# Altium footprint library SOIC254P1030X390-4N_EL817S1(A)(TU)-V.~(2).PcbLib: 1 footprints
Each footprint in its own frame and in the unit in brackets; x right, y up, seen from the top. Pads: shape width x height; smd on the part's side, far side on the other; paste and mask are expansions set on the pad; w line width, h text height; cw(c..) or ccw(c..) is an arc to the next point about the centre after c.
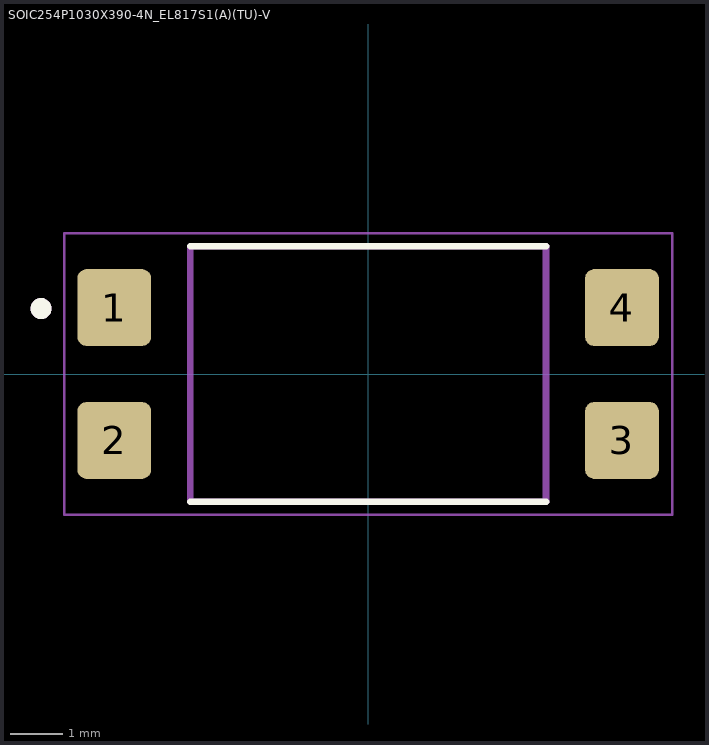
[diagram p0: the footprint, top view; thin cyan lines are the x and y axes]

## SOIC254P1030X390-4N_EL817S1(A)(TU)-V [mm]
pads (4):
  rrect25% 1.41x1.47 smd: 1(-4.85,1.27) 2(-4.85,-1.27) 3(4.85,-1.27) 4(4.85,1.27)
Top Overlay:
  circle w0.2: c-6.25,1.25 r0.1
  lines w0.127: -3.4,-2.44 3.4,-2.44 ; -3.4,2.44 3.4,2.44
Mechanical 13:
  circle w0.2: c-6.25,1.25 r0.1
  lines w0.127: -3.4,-2.44 3.4,-2.44 3.4,2.44 -3.4,2.44 -3.4,-2.44
Mechanical 15:
  lines w0.05: -5.81,-2.69 -5.81,2.69 5.81,2.69 5.81,-2.69 -5.81,-2.69
3D body "EL817S1(C)(TA)-V.STEP": height 3.9, standoff 0, extent -5.023,-2.29 5.277,2.29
